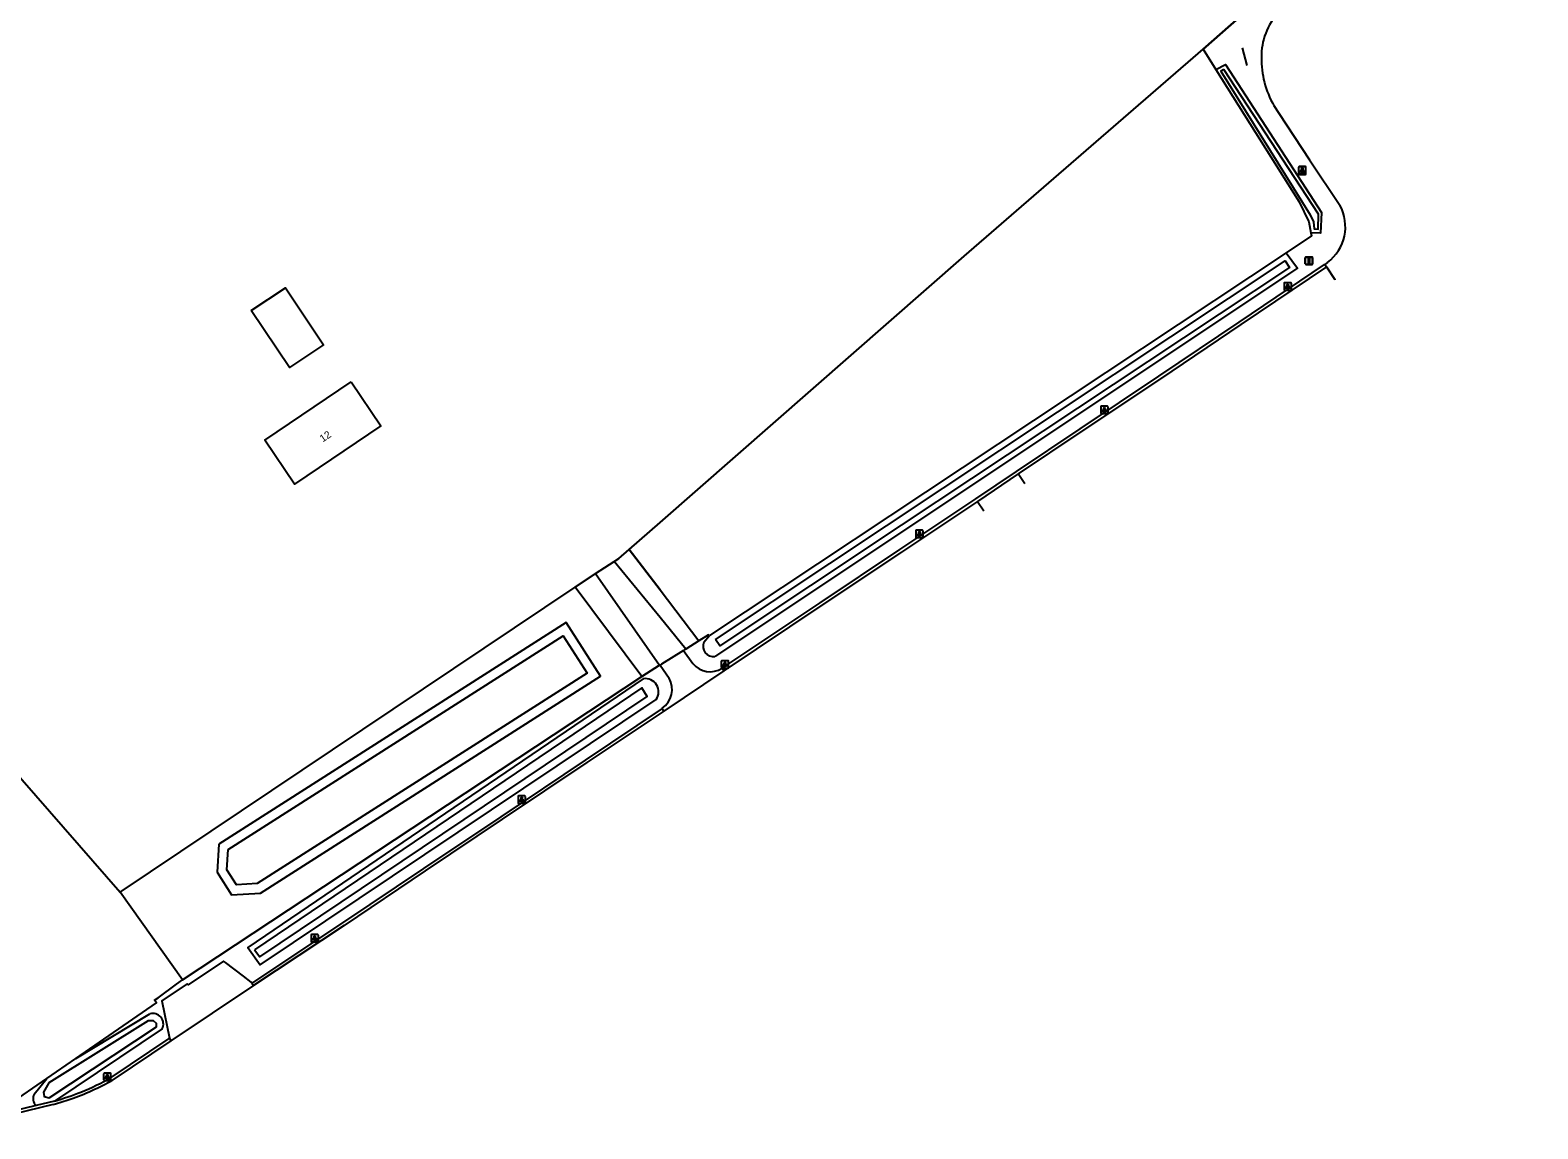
# Model space of a CAD drawing. Extents: x 156502 to 159074, y 384229 to 386094.
# Drawn here: x 158415.1 to 158618.3, y 384268.8 to 384416.9 of the extents above; entities that cross this region are included whole.
import ezdxf

# ---------------------------------------------------------------- set-up
doc = ezdxf.new("R2010")
doc.units = 0
for name, color, linetype in [('IMGEO_Berm_groen', 7, 'Continuous'), ('IMGEO_Gemengd_bos', 7, 'Continuous'), ('IMGEO_Grasland_overig', 7, 'Continuous'), ('IMGEO_Greppel_droge_sloot', 7, 'Continuous'), ('IMGEO_Groenvoorziening', 7, 'Continuous'), ('IMGEO_Hek', 7, 'Continuous'), ('IMGEO_Lichtpunt', 7, 'Continuous'), ('IMGEO_Loofbos', 7, 'Continuous'), ('IMGEO_Pand', 7, 'Continuous'), ('IMGEO_Pand_nummerreeks', 7, 'Continuous'), ('IMGEO_Rijbaan_lokaal_gesloten', 7, 'Continuous'), ('IMGEO_Rijbaan_lokaal_halfverhard', 7, 'Continuous'), ('IMGEO_Rijbaan_lokaal_open', 7, 'Continuous'), ('IMGEO_Verkeersbordpaal', 7, 'Continuous'), ('IMGEO_Waterloop', 7, 'Continuous')]:
    doc.layers.add(name, color=color, linetype=linetype)

msp = doc.modelspace()

# ---------------------------------------------------------------- linework, layer by layer
at = {"layer": 'IMGEO_Berm_groen'}
for points in [[(158435.63, 384288.89), (158497.53, 384329.78)], [(158499.95, 384331.29), (158497.53, 384329.78)], [(158499.95, 384331.29), (158500.02, 384331.33)], [(158497.73, 384329.47), (158444.44, 384293.26), (158446.11, 384290.9), (158499.48, 384326.68)], [(158421.25, 384278.29), (158432.11, 384285.8), (158431.87, 384286.14), (158432.37, 384286.47), (158434.85, 384288.31), (158435.15, 384288.53), (158435.63, 384288.89)], [(158421.25, 384278.29), (158431.23, 384284.32)], [(158432.91, 384282.29), (158418.39, 384272.56)]]:
    msp.add_lwpolyline(points, dxfattribs=at)
for centre, radius, start, end in [((158498.02, 384327.7), 1.79, 325.0453, 99.1903), ((158431.6, 384282.91), 1.46, 334.556, 104.5546)]:
    msp.add_arc(centre, radius, start, end, dxfattribs=at)
at = {"layer": 'IMGEO_Gemengd_bos'}
for points in [[(158573.19, 384414.32), (158670.56, 384500), (158733.14, 384554.95), (158790.51, 384607.91)], [(158495.84, 384346.91), (158500, 384350.54), (158541.01, 384386.46), (158573.19, 384414.32)], [(158493.82, 384345.29), (158494.46, 384345.69), (158495.84, 384346.91)], [(158491.32, 384343.65), (158493.82, 384345.29)], [(158488.58, 384341.8), (158491.32, 384343.65)], [(158427.25, 384300.73), (158488.58, 384341.8)]]:
    msp.add_lwpolyline(points, dxfattribs=at)
at = {"layer": 'IMGEO_Grasland_overig'}
for points in [[(158503.48, 384333.48), (158500, 384337.74), (158493.82, 384345.29)], [(158491.32, 384343.65), (158499.95, 384331.29)], [(158503.48, 384333.48), (158503.28, 384333.36), (158503.18, 384333.29)]]:
    msp.add_lwpolyline(points, dxfattribs=at)
at = {"layer": 'IMGEO_Greppel_droge_sloot'}
msp.add_lwpolyline([(158575.99, 384411.62), (158575.58, 384411.38), (158587.64, 384392), (158588.09, 384391.06), (158588.16, 384390.11), (158588.71, 384390.08), (158588.76, 384392.11), (158575.99, 384411.62)], dxfattribs=at)
at = {"layer": 'IMGEO_Groenvoorziening'}
for points in [[(158573.19, 384414.32), (158574.92, 384411.58)], [(158574.92, 384411.58), (158576.2, 384412.29), (158589.14, 384392.31), (158589.02, 384389.56), (158587.72, 384389.57)], [(158574.92, 384411.58), (158586.13, 384393.74), (158587.44, 384391.07), (158587.72, 384389.57)], [(158587.72, 384389.57), (158587.8, 384389.16), (158584.38, 384386.89)], [(158584.38, 384386.89), (158506.68, 384335.32)], [(158584.38, 384386.89), (158585.91, 384384.8), (158507.39, 384332.46)], [(158495.84, 384346.91), (158500, 384341.46), (158505.25, 384334.58)], [(158497.53, 384329.78), (158488.58, 384341.8)], [(158440.54, 384307.2), (158440.29, 384303.39), (158442.23, 384300.34), (158446.13, 384300.57), (158491.99, 384329.81), (158487.36, 384337.06), (158440.54, 384307.2)], [(158505.25, 384334.58), (158503.48, 384333.48)], [(158506.68, 384335.32), (158506.55, 384335.39), (158505.25, 384334.58)], [(158505.9, 384334.39), (158506.68, 384335.32)], [(158415.64, 384273.48), (158417.33, 384275.58)]]:
    msp.add_lwpolyline(points, dxfattribs=at)
for centre, radius, start, end in [((158507.18, 384333.84), 1.39, 156.7615, 278.7321), ((158416.81, 384272.9), 1.31, 153.4915, 226.6054)]:
    msp.add_arc(centre, radius, start, end, dxfattribs=at)
at = {"layer": 'IMGEO_Hek'}
for points in [[(158670.56, 384500), (158573.19, 384414.32)], [(158495.84, 384346.91), (158500, 384350.54), (158541.01, 384386.46), (158573.19, 384414.32)], [(158573.19, 384414.32), (158574.92, 384411.58)], [(158578.46, 384414.52), (158579.07, 384412.14)], [(158574.92, 384411.58), (158586.13, 384393.74), (158587.44, 384391.07), (158587.72, 384389.57)], [(158587.72, 384389.57), (158587.8, 384389.16), (158584.38, 384386.89)], [(158584.38, 384386.89), (158506.68, 384335.32)], [(158500, 384341.46), (158495.84, 384346.91)], [(158491.32, 384343.65), (158488.58, 384341.8)], [(158427.25, 384300.73), (158488.58, 384341.8)], [(158497.53, 384329.78), (158488.58, 384341.8)], [(158500, 384341.46), (158505.25, 384334.58)], [(158505.25, 384334.58), (158503.48, 384333.48)], [(158506.68, 384335.32), (158506.55, 384335.39), (158505.25, 384334.58)], [(158503.28, 384333.36), (158503.18, 384333.29), (158500.2, 384331.44)], [(158503.48, 384333.48), (158503.28, 384333.36)], [(158421.25, 384278.29), (158432.11, 384285.8), (158431.87, 384286.14), (158432.37, 384286.47), (158434.85, 384288.31), (158435.15, 384288.53), (158435.63, 384288.89), (158497.53, 384329.78)], [(158497.53, 384329.78), (158499.95, 384331.29)], [(158500.2, 384331.44), (158500.02, 384331.33), (158499.95, 384331.29)], [(158435.63, 384288.89), (158427.25, 384300.73)], [(158417.33, 384275.58), (158421.25, 384278.29)], [(158412.28, 384272.08), (158417.33, 384275.58)]]:
    msp.add_lwpolyline(points, dxfattribs=at)
at = {"layer": 'IMGEO_Lichtpunt'}
for p, q in [((158586.06, 384398.42), (158586.06, 384397.61)), ((158586.06, 384398.42), (158586.06, 384397.61)), ((158586.06, 384398.36), (158586.06, 384397.56)), ((158586.06, 384398.36), (158586.06, 384397.56)), ((158586.96, 384398.51), (158586.15, 384398.51)), ((158586.96, 384398.51), (158586.15, 384398.51)), ((158586.96, 384398.46), (158586.15, 384398.46)), ((158586.96, 384398.46), (158586.15, 384398.46)), ((158586.15, 384397.52), (158586.96, 384397.52)), ((158586.15, 384397.52), (158586.96, 384397.52)), ((158586.15, 384397.46), (158586.96, 384397.46)), ((158586.15, 384397.46), (158586.96, 384397.46)), ((158587.05, 384397.61), (158587.05, 384398.42)), ((158587.05, 384397.61), (158587.05, 384398.42)), ((158587.05, 384397.56), (158587.05, 384398.36)), ((158587.05, 384397.56), (158587.05, 384398.36)), ((158584.11, 384382.76), (158584.11, 384381.95)), ((158584.11, 384382.76), (158584.11, 384381.95)), ((158585.01, 384382.85), (158584.21, 384382.85)), ((158585.01, 384382.85), (158584.21, 384382.85)), ((158585.11, 384381.95), (158585.11, 384382.76)), ((158585.11, 384381.95), (158585.11, 384382.76)), ((158584.21, 384381.85), (158585.01, 384381.85)), ((158584.21, 384381.85), (158585.01, 384381.85)), ((158559.4, 384366.13), (158559.4, 384365.33)), ((158559.4, 384366.13), (158559.4, 384365.33)), ((158560.3, 384366.23), (158559.5, 384366.23)), ((158560.3, 384366.23), (158559.5, 384366.23)), ((158559.5, 384365.23), (158560.3, 384365.23)), ((158559.5, 384365.23), (158560.3, 384365.23)), ((158560.4, 384365.33), (158560.4, 384366.13)), ((158560.4, 384365.33), (158560.4, 384366.13)), ((158534.47, 384349.4), (158534.47, 384348.59)), ((158534.47, 384349.4), (158534.47, 384348.59)), ((158535.37, 384349.49), (158534.56, 384349.49)), ((158535.37, 384349.49), (158534.56, 384349.49)), ((158534.56, 384348.5), (158535.37, 384348.5)), ((158534.56, 384348.5), (158535.37, 384348.5)), ((158535.46, 384348.59), (158535.46, 384349.4)), ((158535.46, 384348.59), (158535.46, 384349.4)), ((158508.24, 384331.81), (158508.24, 384331.01)), ((158508.24, 384331.81), (158508.24, 384331.01)), ((158509.15, 384331.91), (158508.34, 384331.91)), ((158509.15, 384331.91), (158508.34, 384331.91)), ((158509.24, 384331.01), (158509.24, 384331.81)), ((158509.24, 384331.01), (158509.24, 384331.81)), ((158508.34, 384330.91), (158509.15, 384330.91)), ((158508.34, 384330.91), (158509.15, 384330.91)), ((158480.86, 384313.59), (158480.86, 384312.78)), ((158480.86, 384313.59), (158480.86, 384312.78)), ((158481.76, 384313.69), (158480.96, 384313.69)), ((158481.76, 384313.69), (158480.96, 384313.69)), ((158481.86, 384312.78), (158481.86, 384313.59)), ((158481.86, 384312.78), (158481.86, 384313.59)), ((158480.96, 384312.69), (158481.76, 384312.69)), ((158480.96, 384312.69), (158481.76, 384312.69)), ((158452.96, 384294.91), (158452.96, 384294.1)), ((158452.96, 384294.91), (158452.96, 384294.1)), ((158453.86, 384295), (158453.06, 384295)), ((158453.86, 384295), (158453.06, 384295)), ((158453.06, 384294.01), (158453.86, 384294.01)), ((158453.06, 384294.01), (158453.86, 384294.01)), ((158453.96, 384294.1), (158453.96, 384294.91)), ((158453.96, 384294.1), (158453.96, 384294.91)), ((158424.99, 384276.22), (158424.99, 384275.42)), ((158424.99, 384276.22), (158424.99, 384275.42)), ((158425.89, 384276.32), (158425.09, 384276.32)), ((158425.89, 384276.32), (158425.09, 384276.32)), ((158425.09, 384275.32), (158425.89, 384275.32)), ((158425.09, 384275.32), (158425.89, 384275.32)), ((158425.99, 384275.42), (158425.99, 384276.22)), ((158425.99, 384275.42), (158425.99, 384276.22))]:
    msp.add_line(p, q, dxfattribs=at)
for points in [[(158586.43, 384398.08), (158586.47, 384398.05), (158586.28, 384397.79), (158586.24, 384397.82), (158586.43, 384398.08)], [(158586.43, 384398.03), (158586.47, 384398), (158586.28, 384397.74), (158586.24, 384397.77), (158586.43, 384398.03)], [(158586.53, 384398.03), (158586.58, 384398.03), (158586.58, 384397.71), (158586.53, 384397.71), (158586.53, 384398.03)], [(158586.53, 384397.98), (158586.58, 384397.98), (158586.58, 384397.66), (158586.53, 384397.66), (158586.53, 384397.98)], [(158586.64, 384398.05), (158586.68, 384398.08), (158586.87, 384397.82), (158586.83, 384397.79), (158586.64, 384398.05)], [(158586.64, 384398), (158586.68, 384398.03), (158586.87, 384397.76), (158586.83, 384397.74), (158586.64, 384398)], [(158584.49, 384382.42), (158584.53, 384382.39), (158584.34, 384382.13), (158584.3, 384382.16), (158584.49, 384382.42)], [(158584.59, 384382.37), (158584.64, 384382.37), (158584.64, 384382.05), (158584.59, 384382.05), (158584.59, 384382.37)], [(158584.7, 384382.39), (158584.74, 384382.42), (158584.92, 384382.16), (158584.89, 384382.13), (158584.7, 384382.39)], [(158559.78, 384365.8), (158559.81, 384365.77), (158559.63, 384365.51), (158559.59, 384365.53), (158559.78, 384365.8)], [(158559.88, 384365.75), (158559.93, 384365.75), (158559.93, 384365.43), (158559.88, 384365.43), (158559.88, 384365.75)], [(158559.99, 384365.77), (158560.03, 384365.8), (158560.21, 384365.53), (158560.17, 384365.51), (158559.99, 384365.77)], [(158534.84, 384349.06), (158534.88, 384349.03), (158534.69, 384348.77), (158534.65, 384348.8), (158534.84, 384349.06)], [(158534.94, 384349.01), (158534.99, 384349.01), (158534.99, 384348.69), (158534.94, 384348.69), (158534.94, 384349.01)], [(158535.05, 384349.03), (158535.09, 384349.06), (158535.28, 384348.8), (158535.24, 384348.77), (158535.05, 384349.03)], [(158508.62, 384331.48), (158508.66, 384331.45), (158508.47, 384331.19), (158508.43, 384331.21), (158508.62, 384331.48)], [(158508.72, 384331.43), (158508.77, 384331.43), (158508.77, 384331.11), (158508.72, 384331.11), (158508.72, 384331.43)], [(158508.83, 384331.45), (158508.87, 384331.48), (158509.06, 384331.21), (158509.02, 384331.19), (158508.83, 384331.45)], [(158481.24, 384313.25), (158481.27, 384313.23), (158481.09, 384312.96), (158481.05, 384312.99), (158481.24, 384313.25)], [(158481.34, 384313.21), (158481.39, 384313.21), (158481.39, 384312.88), (158481.34, 384312.88), (158481.34, 384313.21)], [(158481.45, 384313.23), (158481.49, 384313.25), (158481.67, 384312.99), (158481.63, 384312.96), (158481.45, 384313.23)], [(158453.34, 384294.57), (158453.37, 384294.54), (158453.19, 384294.28), (158453.15, 384294.31), (158453.34, 384294.57)], [(158453.44, 384294.52), (158453.49, 384294.52), (158453.49, 384294.2), (158453.44, 384294.2), (158453.44, 384294.52)], [(158453.55, 384294.54), (158453.59, 384294.57), (158453.77, 384294.31), (158453.73, 384294.28), (158453.55, 384294.54)], [(158425.37, 384275.89), (158425.4, 384275.86), (158425.22, 384275.6), (158425.18, 384275.63), (158425.37, 384275.89)], [(158425.47, 384275.84), (158425.51, 384275.84), (158425.51, 384275.52), (158425.47, 384275.52), (158425.47, 384275.84)], [(158425.58, 384275.86), (158425.62, 384275.89), (158425.8, 384275.62), (158425.76, 384275.6), (158425.58, 384275.86)]]:
    msp.add_lwpolyline(points, dxfattribs=at)
for centre in [(158586.56, 384398.22), (158586.56, 384398.16), (158584.61, 384382.55), (158559.9, 384365.93), (158534.97, 384349.2), (158508.74, 384331.61), (158481.36, 384313.39), (158453.46, 384294.71), (158425.49, 384276.02)]:
    msp.add_circle(centre, 0.0994, dxfattribs=at)
for centre, start, end in [((158586.15, 384398.42), 90, 180), ((158586.15, 384398.42), 90, 180), ((158586.15, 384398.36), 90, 180), ((158586.15, 384398.36), 90, 180), ((158586.15, 384397.61), 180, 270), ((158586.15, 384397.61), 180, 270), ((158586.15, 384397.56), 180, 270), ((158586.15, 384397.56), 180, 270), ((158586.96, 384398.42), 0, 90), ((158586.96, 384398.42), 0, 90), ((158586.96, 384398.36), 0, 90), ((158586.96, 384398.36), 0, 90), ((158586.96, 384397.61), 270, 0), ((158586.96, 384397.61), 270, 360), ((158586.96, 384397.56), 270, 0), ((158586.96, 384397.56), 270, 360), ((158584.21, 384382.76), 90, 180), ((158584.21, 384382.76), 90, 180), ((158585.01, 384382.76), 0, 90), ((158585.01, 384382.76), 0, 90), ((158584.21, 384381.95), 180, 270), ((158584.21, 384381.95), 180, 270), ((158585.01, 384381.95), 270, 0), ((158585.01, 384381.95), 270, 360), ((158559.5, 384366.13), 90, 180), ((158559.5, 384366.13), 90, 180), ((158559.5, 384365.33), 180, 270), ((158559.5, 384365.33), 180, 270), ((158560.3, 384366.13), 0, 90), ((158560.3, 384366.13), 0, 90), ((158560.3, 384365.33), 270, 0), ((158560.3, 384365.33), 270, 360), ((158534.56, 384349.4), 90, 180), ((158534.56, 384349.4), 90, 180), ((158534.56, 384348.59), 180, 270), ((158534.56, 384348.59), 180, 270), ((158535.37, 384349.4), 0, 90), ((158535.37, 384349.4), 0, 90), ((158535.37, 384348.59), 270, 0), ((158535.37, 384348.59), 270, 360), ((158508.34, 384331.81), 90, 180), ((158508.34, 384331.81), 90, 180), ((158509.15, 384331.81), 0, 90), ((158509.15, 384331.81), 0, 90), ((158508.34, 384331.01), 180, 270), ((158508.34, 384331.01), 180, 270), ((158509.15, 384331.01), 270, 0), ((158509.15, 384331.01), 270, 360), ((158480.96, 384313.59), 90, 180), ((158480.96, 384313.59), 90, 180), ((158481.76, 384313.59), 0, 90), ((158481.76, 384313.59), 0, 90), ((158480.96, 384312.78), 180, 270), ((158480.96, 384312.78), 180, 270), ((158481.76, 384312.78), 270, 0), ((158481.76, 384312.78), 270, 360), ((158453.06, 384294.91), 90, 180), ((158453.06, 384294.91), 90, 180), ((158453.06, 384294.1), 180, 270), ((158453.06, 384294.1), 180, 270), ((158453.86, 384294.91), 0, 90), ((158453.86, 384294.91), 0, 90), ((158453.86, 384294.1), 270, 0), ((158453.86, 384294.1), 270, 360), ((158425.09, 384276.22), 90, 180), ((158425.09, 384276.22), 90, 180), ((158425.09, 384275.42), 180, 270), ((158425.09, 384275.42), 180, 270), ((158425.89, 384276.22), 0, 90), ((158425.89, 384276.22), 0, 90), ((158425.89, 384275.42), 270, 0), ((158425.89, 384275.42), 270, 360)]:
    msp.add_arc(centre, 0.0946, start, end, dxfattribs=at)
at = {"layer": 'IMGEO_Loofbos'}
for points in [[(157851.49, 384572.1), (157878.29, 384557.34), (158010.38, 384485.78), (158110.98, 384431.04), (158112.87, 384430.01), (158139.02, 384415.66), (158224.68, 384367.19), (158301.4, 384333.78), (158310.78, 384329.66), (158316.87, 384327), (158330.57, 384320.99), (158353, 384310.09), (158355.76, 384308.75), (158363.15, 384305.15), (158369.4, 384300.97), (158412.28, 384272.08), (158417.33, 384275.58)], [(158378.03, 384357.05), (158427.25, 384300.73)], [(158435.63, 384288.89), (158427.25, 384300.73)], [(158417.33, 384275.58), (158421.25, 384278.29)]]:
    msp.add_lwpolyline(points, dxfattribs=at)
at = {"layer": 'IMGEO_Pand'}
for points in [[(158444.9, 384379.1), (158449.53, 384382.18), (158454.66, 384374.5), (158450.04, 384371.41), (158444.9, 384379.1)], [(158458.38, 384369.51), (158462.39, 384363.57), (158450.74, 384355.71), (158446.73, 384361.65), (158458.38, 384369.51)]]:
    msp.add_lwpolyline(points, dxfattribs=at)
at = {"layer": 'IMGEO_Rijbaan_lokaal_gesloten'}
for points in [[(158589.83, 384384.98), (158578.29, 384377.22), (158567.47, 384369.91), (158556.84, 384362.84), (158548.26, 384357.1)], [(158589.83, 384384.98), (158590.94, 384383.3), (158590.97, 384383.26)], [(158548.26, 384357.1), (158542.79, 384353.39)], [(158549.17, 384355.73), (158548.26, 384357.1)], [(158542.79, 384353.39), (158532.53, 384346.56), (158521.79, 384339.38), (158508.58, 384330.54)], [(158542.79, 384353.39), (158543.65, 384352.09)], [(158508.58, 384330.54), (158500.53, 384325.13)], [(158500.53, 384325.13), (158490.12, 384318.17), (158478.74, 384310.54), (158468.33, 384303.57), (158457.42, 384296.24), (158445.21, 384288.12)], [(158445.21, 384288.12), (158434.07, 384280.66)], [(158434.07, 384280.66), (158426.23, 384275.4)], [(158418.22, 384272.1), (158407.46, 384269.49), (158404.77, 384268.81), (158404.62, 384269.18)]]:
    msp.add_lwpolyline(points, dxfattribs=at)
for centre, radius, start, end in [((158409.43, 384304.82), 33.88, 289.1007, 299.7359), ((158409.57, 384304.41), 33.45, 284.99, 289.0995)]:
    msp.add_arc(centre, radius, start, end, dxfattribs=at)
at = {"layer": 'IMGEO_Rijbaan_lokaal_halfverhard'}
for points in [[(158508.39, 384330.9), (158521.57, 384339.71), (158532.31, 384346.89), (158542.58, 384353.73), (158548.03, 384357.43), (158556.62, 384363.17), (158567.25, 384370.25), (158578.06, 384377.55), (158589.58, 384385.32), (158589.6, 384385.33)], [(158500.3, 384325.46), (158489.9, 384318.5), (158478.52, 384310.87), (158468.1, 384303.9), (158457.2, 384296.58), (158444.99, 384288.46)], [(158426.03, 384275.74), (158433.85, 384280.99), (158433.88, 384281.01)], [(158415.91, 384271.95), (158407.37, 384269.88), (158404.62, 384269.18)], [(158418.39, 384272.56), (158415.91, 384271.95)]]:
    msp.add_lwpolyline(points, dxfattribs=at)
for centre, radius, start, end in [((158409.55, 384304.56), 33.19, 291.9275, 299.7688), ((158409.54, 384304.51), 33.15, 285.4732, 291.9749)]:
    msp.add_arc(centre, radius, start, end, dxfattribs=at)
at = {"layer": 'IMGEO_Rijbaan_lokaal_open'}
for points in [[(158582.75, 384406.74), (158583.41, 384405.7), (158587.54, 384399.41), (158591.63, 384393.3)], [(158589.98, 384385.6), (158589.6, 384385.33)], [(158589.6, 384385.33), (158589.83, 384384.98)], [(158503.18, 384333.29), (158500.2, 384331.44), (158500.02, 384331.33)], [(158503.18, 384333.29), (158504.41, 384331.54)], [(158500.02, 384331.33), (158501.22, 384329.54)], [(158508.38, 384330.91), (158508.39, 384330.9)], [(158508.39, 384330.9), (158508.58, 384330.54)], [(158500.27, 384325.52), (158500.3, 384325.46)], [(158500.53, 384325.13), (158500.3, 384325.46)], [(158444.99, 384288.46), (158444.89, 384288.59), (158443.84, 384289.39), (158441.42, 384291.21), (158441.18, 384291.39), (158436.39, 384288.2), (158436.28, 384288.36), (158432.85, 384286.08), (158433.88, 384281.01)], [(158444.99, 384288.46), (158445.21, 384288.12)], [(158433.88, 384281.01), (158433.88, 384280.99), (158434.07, 384280.66)]]:
    msp.add_lwpolyline(points, dxfattribs=at)
for centre, radius, start, end in [((158589.54, 384413.44), 8.48, 136.355, 181.437), ((158593.29, 384412.94), 12.23, 178.6694, 210.4774), ((158586.34, 384390.41), 6.03, 307.1121, 28.67), ((158506.74, 384333.41), 2.98, 218.6163, 303.3303), ((158498.6, 384328.04), 3.02, 303.4638, 29.7821)]:
    msp.add_arc(centre, radius, start, end, dxfattribs=at)
at = {"layer": 'IMGEO_Verkeersbordpaal'}
for p, q in [((158586.96, 384385.42), (158586.96, 384386.22)), ((158586.96, 384386.22), (158586.96, 384385.42)), ((158587.06, 384386.32), (158587.85, 384386.32)), ((158587.85, 384386.32), (158587.06, 384386.32)), ((158587.85, 384385.32), (158587.06, 384385.32)), ((158587.06, 384385.32), (158587.85, 384385.32)), ((158587.95, 384386.22), (158587.95, 384385.42)), ((158587.95, 384385.42), (158587.95, 384386.22))]:
    msp.add_line(p, q, dxfattribs=at)
msp.add_lwpolyline([(158587.38, 384386.2), (158587.53, 384386.2), (158587.53, 384385.45), (158587.38, 384385.45), (158587.38, 384386.2)], dxfattribs=at)
for centre, start, end in [((158587.06, 384386.22), 90, 180), ((158587.06, 384386.22), 90, 180), ((158587.06, 384385.42), 180, 270), ((158587.06, 384385.42), 180, 270), ((158587.85, 384386.22), 0, 90), ((158587.85, 384386.22), 360, 90), ((158587.85, 384385.42), 270, 0), ((158587.85, 384385.42), 270, 0)]:
    msp.add_arc(centre, 0.1, start, end, dxfattribs=at)
at = {"layer": 'IMGEO_Waterloop'}
for points in [[(158507.49, 384334.78), (158584.27, 384385.82), (158584.86, 384384.93), (158532.51, 384350.16), (158508.05, 384333.93), (158507.49, 384334.78)], [(158441.81, 384306.45), (158486.96, 384335.24), (158490.17, 384330.22), (158445.71, 384301.87), (158442.93, 384301.7), (158441.63, 384303.73), (158441.81, 384306.45)], [(158445.35, 384292.94), (158446.07, 384292), (158498.28, 384327.1), (158497.56, 384328.24), (158445.35, 384292.94)], [(158416.9, 384273.75), (158417, 384273.16), (158417.65, 384272.99), (158432.11, 384282.57), (158432.11, 384283.01), (158431.73, 384283.35), (158431.03, 384283.35), (158417.63, 384275), (158416.9, 384273.75)]]:
    msp.add_lwpolyline(points, dxfattribs=at)

# ---------------------------------------------------------------- texts
at = {"layer": 'IMGEO_Pand_nummerreeks'}
msp.add_text('12', height=1, rotation=34.0068, dxfattribs=at).set_placement((158454.54, 384361.32))

doc.saveas('drawing.dxf')
